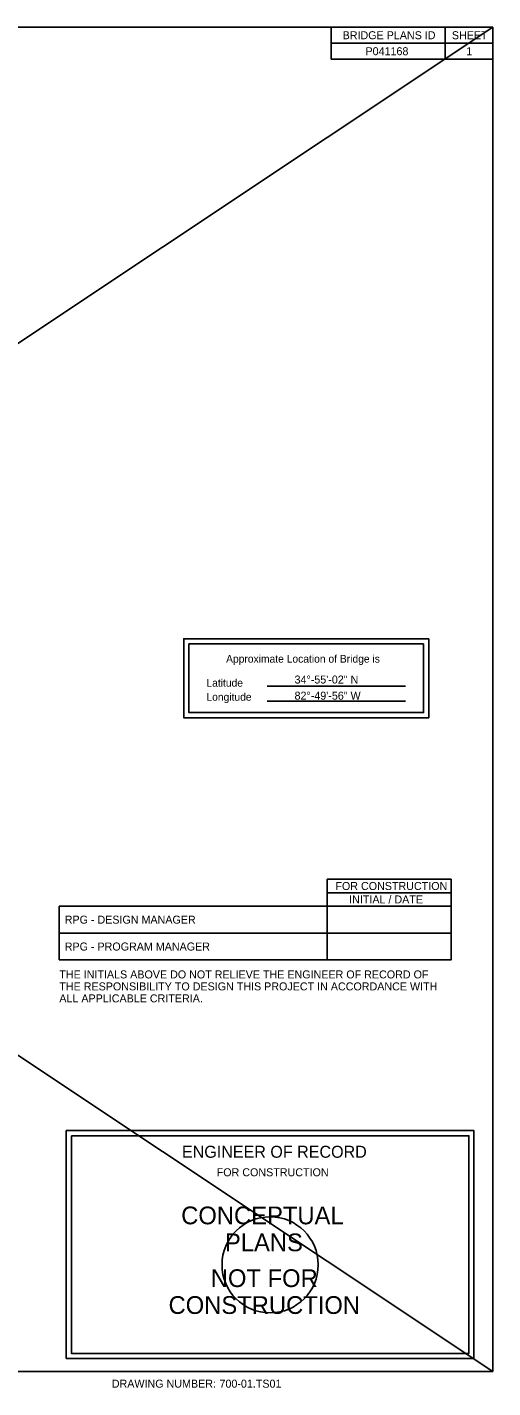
# Model space of a CAD drawing. Extents: x -2.9 to 3.9, y -2.5 to 1.79.
# Drawn here: x -0.814 to -0.208, y 0.02 to 1.792 of the extents above; entities that cross this region are included whole.
import ezdxf

# ---------------------------------------------------------------- set-up
doc = ezdxf.new("R2010")
doc.units = 0
for name, color, linetype in [('BR_AUTO DIMENSION', 7, 'Continuous'), ('BR_BORDER LINES', 7, 'Continuous'), ('BR_DETAILS', 7, 'Continuous'), ('Default', 7, 'Continuous'), ('NoPlot', 7, 'Continuous')]:
    doc.layers.add(name, color=color, linetype=linetype)

msp = doc.modelspace()

# ---------------------------------------------------------------- linework, layer by layer
at = {"layer": 'BR_BORDER LINES'}
for p, q in [((-0.4185, 1.7917), (-0.4185, 1.75)), ((-0.27, 1.7917), (-0.27, 1.75)), ((-0.2083, 1.7708), (-0.4185, 1.7708)), ((-0.2083, 1.75), (-0.4185, 1.75)), ((-0.4235, 0.6823), (-0.2625, 0.6823)), ((-0.4235, 0.5773), (-0.4235, 0.6823)), ((-0.2625, 0.6823), (-0.2625, 0.5773)), ((-0.4235, 0.6648), (-0.2625, 0.6648)), ((-0.7722, 0.6473), (-0.2625, 0.6473)), ((-0.7722, 0.5773), (-0.7722, 0.6473)), ((-0.7722, 0.6123), (-0.2625, 0.6123)), ((-0.7722, 0.5773), (-0.2625, 0.5773))]:
    msp.add_line(p, q, dxfattribs=at)
for points in [[(-2.8333, 1.7917), (-0.2083, 1.7917), (-0.2083, 0.0417), (-2.8333, 0.0417)], [(-0.4235, 0.6473), (-0.2625, 0.6473), (-0.2625, 0.6123), (-0.4235, 0.6123)], [(-0.4235, 0.6123), (-0.2625, 0.6123), (-0.2625, 0.5773), (-0.4235, 0.5773)]]:
    msp.add_lwpolyline(points, close=True, dxfattribs=at)
at = {"layer": 'BR_DETAILS'}
for p, q in [((-0.5018, 0.9337), (-0.3216, 0.9337)), ((-0.5018, 0.9144), (-0.3216, 0.9144))]:
    msp.add_line(p, q, dxfattribs=at)
for points in [[(-0.2916, 0.9954), (-0.61, 0.9954), (-0.61, 0.8927), (-0.2916, 0.8927)], [(-0.2983, 0.9887), (-0.6034, 0.9887), (-0.6034, 0.8994), (-0.2983, 0.8994)], [(-0.7628, 0.3551), (-0.2328, 0.3551), (-0.2328, 0.0585), (-0.7628, 0.0585)], [(-0.7561, 0.3485), (-0.2394, 0.3485), (-0.2394, 0.0651), (-0.7561, 0.0651)]]:
    msp.add_lwpolyline(points, close=True, dxfattribs=at)
at = {"layer": 'Default'}
for p, q in [((-2.8333, 1.7917), (-0.2083, 0.0417)), ((-2.8333, 0.0417), (-0.2083, 1.7917))]:
    msp.add_line(p, q, dxfattribs=at)
at = {"layer": 'NoPlot'}
msp.add_line((-0.4978, 0.1804), (-0.4978, 0.1804), dxfattribs=at)
msp.add_circle((-0.4978, 0.1804), 0.0625, dxfattribs=at)

# ---------------------------------------------------------------- texts
at = {"layer": 'BR_AUTO DIMENSION'}
for s, p in [('34°-55\'-02" N', (-0.466, 0.9372)), ('82°-49\'-56" W', (-0.466, 0.9162))]:
    msp.add_text(s, height=0.010417, dxfattribs=at).set_placement(p)
at = {"layer": 'BR_DETAILS'}
for s, p in [('Approximate Location of Bridge is', (-0.555, 0.9644)), ('Latitude', (-0.5806, 0.9331)), ('Longitude', (-0.5806, 0.9148))]:
    msp.add_text(s, height=0.01, dxfattribs=at).set_placement(p)
for s, height, p in [('CONCEPTUAL', 0.02311, (-0.6134, 0.2332)), ('PLANS', 0.02311, (-0.5565, 0.1981)), ('NOT FOR', 0.02311, (-0.5749, 0.1515)), ('CONSTRUCTION', 0.023108, (-0.6298, 0.1165))]:
    msp.add_text(s, height=height, rotation=360, dxfattribs=at).set_placement(p)
at = {"layer": 'Default'}
for s, height, p in [('BRIDGE PLANS ID', 0.010417, (-0.4035, 1.776)), ('SHEET', 0.01042, (-0.2615, 1.776)), ('P041168', 0.01042, (-0.3738, 1.7552)), ('1', 0.0104, (-0.2428, 1.7552)), ('RPG - DESIGN MANAGER', 0.010417, (-0.7648, 0.6246)), ('RPG - PROGRAM MANAGER', 0.010417, (-0.7648, 0.5896)), ('THE INITIALS ABOVE DO NOT RELIEVE THE ENGINEER OF RECORD OF ', 0.010417, (-0.7718, 0.5533)), ('ALL APPLICABLE CRITERIA.', 0.010417, (-0.7718, 0.5221)), ('THE RESPONSIBILITY TO DESIGN THIS PROJECT IN ACCORDANCE WITH ', 0.010417, (-0.7718, 0.5377)), ('ENGINEER OF RECORD', 0.015625, (-0.6124, 0.3198)), ('FOR CONSTRUCTION', 0.010417, (-0.5672, 0.2957)), ('DRAWING NUMBER:', 0.010417, (-0.7036, 0.0205)), ('700-01.TS01', 0.010417, (-0.5636, 0.0205))]:
    msp.add_text(s, height=height, dxfattribs=at).set_placement(p)
for s, p in [('FOR CONSTRUCTION', (-0.4129, 0.6684)), ('INITIAL / DATE', (-0.395, 0.6509))]:
    msp.add_text(s, height=0.010417, rotation=360, dxfattribs=at).set_placement(p)

doc.saveas('drawing.dxf')
